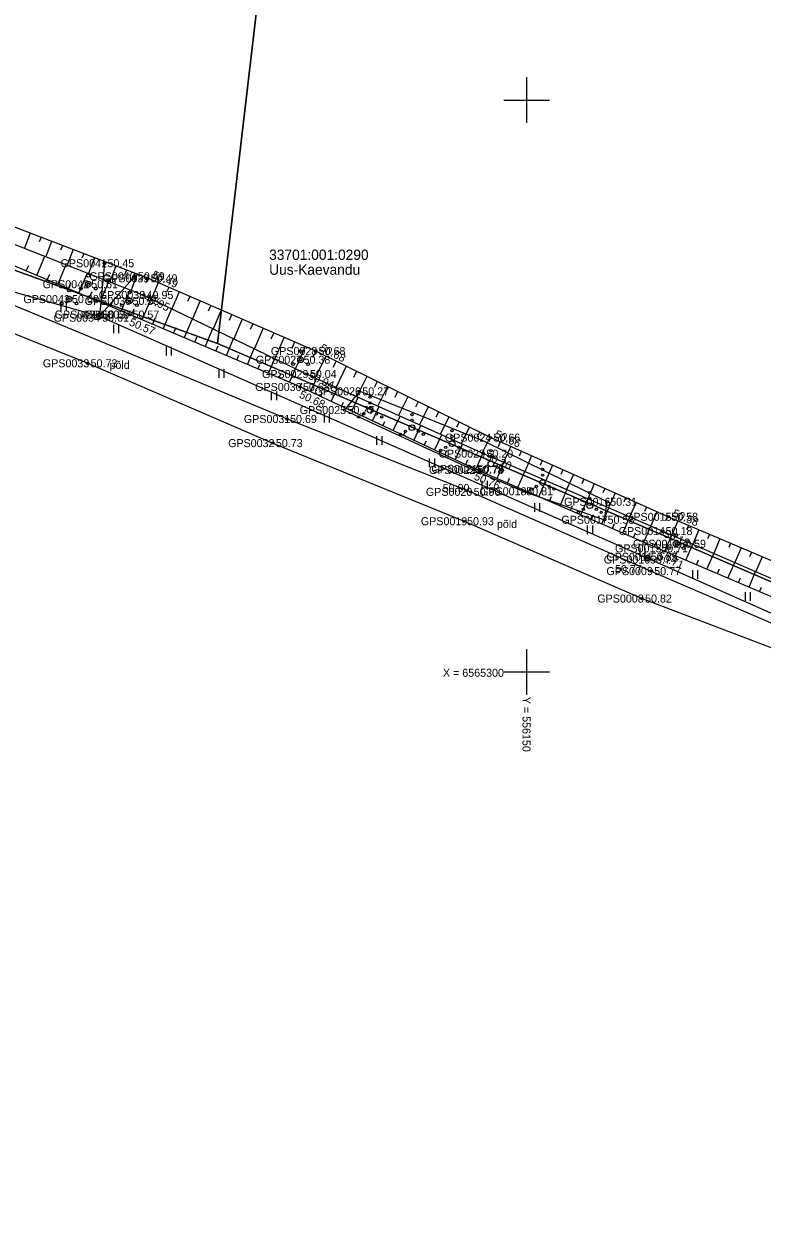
# Model space of a CAD drawing. Extents: x 551623 to 559850, y 6561220 to 6567135.
# Drawn here: x 556106 to 556170.6, y 6565252.6 to 6565356.7 of the extents above; entities that cross this region are included whole.
import ezdxf

# ---------------------------------------------------------------- set-up
doc = ezdxf.new("R2010")
doc.units = 0
for name, color, linetype in [('HALJASTUS', 7, 'Continuous'), ('KORGUS-EH2000', 7, 'Continuous'), ('KPOHULIIN', 7, 'Continuous'), ('MOOTKORG-EH2000', 7, 'Continuous'), ('MOOTMPUNKT', 7, 'Continuous'), ('MOOTNR', 7, 'Continuous'), ('MOOTPIIR', 7, 'Continuous'), ('PIIR', 7, 'Continuous'), ('POST', 7, 'Continuous'), ('PUU', 7, 'Continuous'), ('RELJEEF', 7, 'Continuous'), ('VORK', 7, 'Continuous')]:
    doc.layers.add(name, color=color, linetype=linetype)

msp = doc.modelspace()

# ---------------------------------------------------------------- linework, layer by layer
at = {"layer": 'HALJASTUS'}
for p, q in [((556109.26, 6565332.35), (556109.26, 6565331.59)), ((556109.72, 6565332.35), (556109.72, 6565331.59)), ((556113.87, 6565330.39), (556113.87, 6565329.63)), ((556114.32, 6565330.39), (556114.32, 6565329.63)), ((556118.47, 6565328.44), (556118.47, 6565327.68)), ((556118.92, 6565328.44), (556118.92, 6565327.68)), ((556123.07, 6565326.49), (556123.07, 6565325.73)), ((556123.53, 6565326.49), (556123.53, 6565325.73)), ((556127.67, 6565324.53), (556127.67, 6565323.77)), ((556128.13, 6565324.53), (556128.13, 6565323.77)), ((556132.28, 6565322.58), (556132.28, 6565321.82)), ((556132.73, 6565322.58), (556132.73, 6565321.82)), ((556136.88, 6565320.63), (556136.88, 6565319.87)), ((556137.33, 6565320.63), (556137.33, 6565319.87)), ((556141.48, 6565318.67), (556141.48, 6565317.91)), ((556141.94, 6565318.67), (556141.94, 6565317.91)), ((556146.09, 6565316.72), (556146.09, 6565315.96)), ((556146.54, 6565316.72), (556146.54, 6565315.96)), ((556150.69, 6565314.77), (556150.69, 6565314.01)), ((556151.14, 6565314.77), (556151.14, 6565314.01)), ((556155.29, 6565312.82), (556155.29, 6565312.05)), ((556155.75, 6565312.82), (556155.75, 6565312.05)), ((556159.89, 6565310.86), (556159.89, 6565310.1)), ((556160.35, 6565310.86), (556160.35, 6565310.1)), ((556164.5, 6565308.91), (556164.5, 6565308.15)), ((556164.95, 6565308.91), (556164.95, 6565308.15)), ((556169.1, 6565306.97), (556169.1, 6565306.21)), ((556169.56, 6565306.97), (556169.56, 6565306.21))]:
    msp.add_line(p, q, dxfattribs=at)
for points in [[(556046.78, 6565342.99), (556063.16, 6565343.59), (556068.98, 6565343.23), (556088, 6565339.17), (556129.05, 6565322.12), (556145.11, 6565315.75), (556160.9, 6565308.82), (556181.24, 6565300.03), (556189.31, 6565297.32), (556192.7, 6565293.43)], [(556157.05, 6565314.88), (556146.32, 6565320.15), (556135.37, 6565324.54), (556134.07, 6565322.9), (556145.38, 6565317.66), (556149.71, 6565315.8), (556156.82, 6565313.31), (556157.05, 6565314.88)]]:
    msp.add_lwpolyline(points, dxfattribs=at)
for centre, radius in [((556136.31, 6565324.03), 0.1), ((556136.31, 6565323.53), 0.1), ((556135.74, 6565322.55), 0.1), ((556136.31, 6565322.88), 0.25), ((556136.87, 6565322.55), 0.1), ((556139.97, 6565322.51), 0.1), ((556135.31, 6565322.3), 0.1), ((556137.31, 6565322.3), 0.1), ((556139.97, 6565321.36), 0.25), ((556139.97, 6565322.01), 0.1), ((556138.97, 6565320.78), 0.1), ((556139.4, 6565321.03), 0.1), ((556140.53, 6565321.03), 0.1), ((556140.97, 6565320.78), 0.1), ((556143.48, 6565321.11), 0.1), ((556143.48, 6565320.61), 0.1), ((556142.48, 6565319.39), 0.1), ((556142.92, 6565319.64), 0.1), ((556143.48, 6565319.96), 0.25), ((556144.05, 6565319.64), 0.1), ((556144.48, 6565319.39), 0.1), ((556146.88, 6565319.35), 0.1), ((556146.88, 6565318.2), 0.25), ((556146.88, 6565318.85), 0.1), ((556145.88, 6565317.63), 0.1), ((556146.31, 6565317.88), 0.1), ((556147.44, 6565317.88), 0.1), ((556147.88, 6565317.63), 0.1), ((556151.4, 6565317.71), 0.1), ((556150.84, 6565316.24), 0.1), ((556151.4, 6565316.56), 0.25), ((556151.4, 6565317.21), 0.1), ((556151.97, 6565316.24), 0.1), ((556150.4, 6565315.99), 0.1), ((556152.4, 6565315.99), 0.1), ((556155.52, 6565315.69), 0.1), ((556155.52, 6565315.19), 0.1), ((556154.96, 6565314.22), 0.1), ((556155.52, 6565314.54), 0.25), ((556156.09, 6565314.22), 0.1), ((556154.52, 6565313.97), 0.1), ((556156.52, 6565313.97), 0.1)]:
    msp.add_circle(centre, radius, dxfattribs=at)
at = {"layer": 'KORGUS-EH2000'}
for centre in [(556116.86, 6565334.42), (556116.5, 6565332.96), (556115.27, 6565331.25), (556131.55, 6565328.06), (556111.61, 6565326.99), (556130.78, 6565326.05), (556130.18, 6565324.92), (556129.05, 6565322.12), (556146.84, 6565320.49), (556127.81, 6565320.01), (556146.22, 6565319.09), (556145.45, 6565317.76), (556145.11, 6565315.75), (556144.53, 6565313.18), (556162.39, 6565313.57), (556161.9, 6565312.32), (556161.51, 6565310.81), (556160.9, 6565308.82), (556160.1, 6565306.42)]:
    msp.add_circle(centre, 0.1, dxfattribs=at)
at = {"layer": 'KPOHULIIN'}
msp.add_lwpolyline([(555766.29, 6565358.13), (555774.48, 6565357.81), (555774.48, 6565357.81), (555822.76, 6565358.14), (555870.36, 6565358.42), (555918.91, 6565358.62), (555918.91, 6565358.62), (555966.51, 6565359.06), (556012.01, 6565359.61), (556063.1, 6565345.17), (556063.1, 6565345.17), (556112.63, 6565331.11), (556160.57, 6565309.95), (556211.02, 6565287.53)], dxfattribs=at)
at = {"layer": 'MOOTMPUNKT'}
for centre in [(556113.08, 6565335.74), (556111.66, 6565333.9), (556115.74, 6565334.6), (556116.86, 6565334.42), (556116.5, 6565332.96), (556109.98, 6565332.6), (556115.27, 6565332.44), (556112.62, 6565330.98), (556112.64, 6565331.25), (556115.27, 6565331.25), (556131.55, 6565328.06), (556111.61, 6565326.99), (556130.23, 6565327.3), (556130.78, 6565326.05), (556130.18, 6565324.92), (556135.37, 6565324.54), (556134.07, 6565322.9), (556129.05, 6565322.12), (556146.84, 6565320.49), (556127.81, 6565320.01), (556146.22, 6565319.09), (556145.38, 6565317.66), (556145.45, 6565317.76), (556145.11, 6565315.75), (556149.71, 6565315.8), (556157.05, 6565314.88), (556144.53, 6565313.18), (556156.82, 6565313.31), (556162.39, 6565313.57), (556161.9, 6565312.32), (556163.08, 6565311.21), (556160.6, 6565310.07), (556161.51, 6565310.81), (556160.53, 6565309.83), (556160.9, 6565308.82), (556160.1, 6565306.42)]:
    msp.add_circle(centre, 0.1, dxfattribs=at)
at = {"layer": 'MOOTPIIR'}
for points in [[(556317.29, 6565325.67), (556298.01, 6565323.15), (556292.39, 6565325.24), (556233.7, 6565312.98), (556223.17, 6565308.85), (556214.05, 6565308.49), (556203.22, 6565309.4), (556197.61, 6565310.79), (556194.43, 6565307.33), (556191.93, 6565304.8), (556191.35, 6565302.57), (556183.62, 6565304.52), (556162.39, 6565313.57), (556146.84, 6565320.49), (556131.55, 6565328.06), (556116.86, 6565334.42), (556089.68, 6565344.85), (556063.9, 6565353.52), (556057.93, 6565353.82), (556039.2, 6565356.19)], [(556038.74, 6565344.78), (556063.16, 6565343.59), (556086.72, 6565336.99), (556111.61, 6565326.99), (556127.81, 6565320.01), (556144.53, 6565313.18), (556160.1, 6565306.42), (556180.24, 6565298.77), (556192.7, 6565293.43), (556201.96, 6565286.07), (556200.43, 6565280.1), (556196.23, 6565270.78), (556185.47, 6565248.99)]]:
    msp.add_lwpolyline(points, dxfattribs=at)
at = {"layer": 'PIIR'}
for points in [[(555860.69, 6565787.05), (556134.83, 6565867.67), (556136.76, 6565868.24), (556138.68, 6565868.81), (556304.72, 6565917.64), (556407.28, 6565947.65), (556409.2, 6565948.21), (556411.12, 6565948.77), (556555.39, 6565990.98), (556602.55, 6565855.41), (556340.11, 6565662.55), (556145.23, 6565518.55), (556122.95, 6565328.71), (556065.95, 6565349.3), (555986.85, 6565360.88), (555889.86, 6565359.34), (555877.35, 6565546.73)], [(556340.11, 6565662.55), (556389.4, 6565609.96), (556364.34, 6565374.53), (556350.73, 6565342.07), (556335.44, 6565331.24), (556229.81, 6565311.25), (556213.87, 6565303.19), (556199.38, 6565295.85), (556122.95, 6565328.71), (556145.23, 6565518.55)], [(555766.77, 6565362.31), (555785.15, 6565359.9), (555792.17, 6565359.86), (555889.86, 6565359.34), (555986.85, 6565360.88), (556065.95, 6565349.3), (556122.95, 6565328.71), (556199.38, 6565295.85), (556198.85, 6565282.81), (556195.83, 6565275.41), (556189.32, 6565262.35), (556176.88, 6565235.57), (556133.25, 6565139.15), (556097.67, 6565060.64), (555982.17, 6564796.57), (555965.54, 6564731.83), (555935.2, 6564801.96), (555871.92, 6565015.39), (555870.22, 6565021.13), (555867.36, 6565030.76)]]:
    msp.add_lwpolyline(points, close=True, dxfattribs=at)
at = {"layer": 'POST'}
msp.add_lwpolyline([(556113.08, 6565335.74), (556112.63, 6565331.11), (556115.74, 6565334.6)], dxfattribs=at)
for centre, radius in [((556113.08, 6565335.74), 0.125), ((556113.08, 6565335.74), 0.105), ((556113.08, 6565335.74), 0.0851), ((556113.08, 6565335.74), 0.0651), ((556113.08, 6565335.74), 0.0451), ((556113.08, 6565335.74), 0.0251), ((556113.08, 6565335.74), 0.00511), ((556115.74, 6565334.6), 0.125), ((556115.74, 6565334.6), 0.105), ((556115.74, 6565334.6), 0.0851), ((556115.74, 6565334.6), 0.0651), ((556115.74, 6565334.6), 0.0451), ((556115.74, 6565334.6), 0.0251), ((556115.74, 6565334.6), 0.00511), ((556112.63, 6565331.11), 0.25), ((556160.57, 6565309.95), 0.25)]:
    msp.add_circle(centre, radius, dxfattribs=at)
at = {"layer": 'PUU'}
for centre, radius in [((556111.66, 6565333.9), 0.25), ((556111.66, 6565334.65), 0.125), ((556109.98, 6565333.35), 0.125), ((556111.01, 6565333.52), 0.125), ((556112.31, 6565333.52), 0.125), ((556115.27, 6565333.19), 0.125), ((556109.33, 6565332.22), 0.125), ((556109.98, 6565332.6), 0.25), ((556110.63, 6565332.22), 0.125), ((556114.62, 6565332.07), 0.125), ((556115.27, 6565332.44), 0.25), ((556115.92, 6565332.07), 0.125), ((556130.23, 6565328.05), 0.125), ((556129.58, 6565326.92), 0.125), ((556130.23, 6565327.3), 0.25), ((556130.88, 6565326.92), 0.125), ((556163.08, 6565311.21), 0.25), ((556163.08, 6565311.96), 0.125), ((556162.43, 6565310.83), 0.125), ((556163.73, 6565310.83), 0.125)]:
    msp.add_circle(centre, radius, dxfattribs=at)
at = {"layer": 'RELJEEF'}
for p, q in [((556106.59, 6565338.36), (556106.09, 6565337.05)), ((556107.53, 6565338.01), (556107.38, 6565337.61)), ((556108.46, 6565337.65), (556107.95, 6565336.32)), ((556109.4, 6565337.29), (556109.24, 6565336.89)), ((556107.16, 6565334.67), (556107.87, 6565336.35)), ((556110.33, 6565336.93), (556109.81, 6565335.59)), ((556111.26, 6565336.57), (556111.11, 6565336.17)), ((556112.2, 6565336.21), (556111.67, 6565334.85)), ((556106.24, 6565335.06), (556106.45, 6565335.55)), ((556109, 6565333.89), (556109.73, 6565335.62)), ((556113.13, 6565335.86), (556112.97, 6565335.45)), ((556114.06, 6565335.5), (556113.54, 6565334.12)), ((556115, 6565335.14), (556114.84, 6565334.72)), ((556108.08, 6565334.28), (556108.3, 6565334.79)), ((556109.92, 6565333.5), (556110.14, 6565334.03)), ((556110.84, 6565333.11), (556111.59, 6565334.89)), ((556112.69, 6565332.34), (556113.45, 6565334.15)), ((556115.93, 6565334.78), (556115.4, 6565333.39)), ((556116.86, 6565334.42), (556116.69, 6565334.01)), ((556117.78, 6565334.02), (556117.18, 6565332.63)), ((556111.77, 6565332.73), (556111.99, 6565333.26)), ((556114.53, 6565331.56), (556115.32, 6565333.42)), ((556118.7, 6565333.63), (556118.51, 6565333.2)), ((556119.62, 6565333.23), (556118.98, 6565331.76)), ((556113.61, 6565331.95), (556113.84, 6565332.5)), ((556116.37, 6565330.78), (556117.16, 6565332.64)), ((556120.53, 6565332.83), (556120.34, 6565332.38)), ((556121.45, 6565332.44), (556120.78, 6565330.89)), ((556122.37, 6565332.04), (556122.16, 6565331.56)), ((556115.45, 6565331.17), (556115.69, 6565331.74)), ((556117.29, 6565330.39), (556117.52, 6565330.93)), ((556118.21, 6565330), (556118.96, 6565331.77)), ((556120.06, 6565329.22), (556120.77, 6565330.89)), ((556123.29, 6565331.64), (556122.58, 6565330.01)), ((556124.2, 6565331.24), (556123.99, 6565330.74)), ((556119.13, 6565329.61), (556119.35, 6565330.13)), ((556121.9, 6565328.44), (556122.57, 6565330.02)), ((556125.12, 6565330.85), (556124.38, 6565329.14)), ((556126.04, 6565330.45), (556125.81, 6565329.93)), ((556126.96, 6565330.05), (556126.19, 6565328.27)), ((556120.98, 6565328.83), (556121.18, 6565329.32)), ((556123.74, 6565327.66), (556124.37, 6565329.15)), ((556127.88, 6565329.65), (556127.64, 6565329.11)), ((556128.79, 6565329.26), (556127.99, 6565327.4)), ((556129.71, 6565328.86), (556129.46, 6565328.29)), ((556122.82, 6565328.05), (556123.01, 6565328.51)), ((556125.58, 6565326.88), (556126.17, 6565328.28)), ((556130.63, 6565328.46), (556129.79, 6565326.52)), ((556131.55, 6565328.06), (556131.26, 6565327.49)), ((556124.66, 6565327.27), (556124.84, 6565327.7)), ((556126.5, 6565326.48), (556126.67, 6565326.89)), ((556127.42, 6565326.09), (556127.98, 6565327.4)), ((556132.44, 6565327.62), (556131.5, 6565325.72)), ((556133.34, 6565327.18), (556133.06, 6565326.62)), ((556134.23, 6565326.73), (556133.33, 6565324.9)), ((556128.34, 6565325.7), (556128.5, 6565326.08)), ((556129.26, 6565325.31), (556129.78, 6565326.53)), ((556131.09, 6565324.5), (556131.63, 6565325.66)), ((556135.13, 6565326.29), (556134.86, 6565325.75)), ((556136.03, 6565325.84), (556135.15, 6565324.08)), ((556130.18, 6565324.92), (556130.34, 6565325.27)), ((556132.9, 6565323.65), (556133.46, 6565324.84)), ((556136.92, 6565325.4), (556136.66, 6565324.88)), ((556137.82, 6565324.96), (556136.98, 6565323.26)), ((556131.99, 6565324.07), (556132.16, 6565324.43)), ((556133.8, 6565323.22), (556133.97, 6565323.58)), ((556134.71, 6565322.8), (556135.28, 6565324.02)), ((556138.71, 6565324.51), (556138.47, 6565324.01)), ((556139.61, 6565324.07), (556138.8, 6565322.43)), ((556140.51, 6565323.62), (556140.27, 6565323.14)), ((556135.61, 6565322.37), (556135.79, 6565322.74)), ((556136.52, 6565321.95), (556137.1, 6565323.2)), ((556141.4, 6565323.18), (556140.63, 6565321.61)), ((556142.3, 6565322.73), (556142.07, 6565322.27)), ((556137.42, 6565321.52), (556137.6, 6565321.9)), ((556138.33, 6565321.1), (556138.93, 6565322.38)), ((556140.14, 6565320.25), (556140.75, 6565321.56)), ((556143.19, 6565322.29), (556142.45, 6565320.79)), ((556144.09, 6565321.85), (556143.87, 6565321.41)), ((556139.23, 6565320.67), (556139.42, 6565321.06)), ((556141.95, 6565319.4), (556142.58, 6565320.73)), ((556144.99, 6565321.4), (556144.28, 6565319.97)), ((556145.88, 6565320.96), (556145.67, 6565320.54)), ((556146.78, 6565320.51), (556146.1, 6565319.15)), ((556141.04, 6565319.83), (556141.23, 6565320.22)), ((556143.76, 6565318.55), (556144.4, 6565319.91)), ((556147.69, 6565320.11), (556147.51, 6565319.69)), ((556148.6, 6565319.7), (556147.99, 6565318.33)), ((556142.86, 6565318.98), (556143.05, 6565319.38)), ((556144.67, 6565318.13), (556144.86, 6565318.54)), ((556145.57, 6565317.71), (556146.18, 6565319.11)), ((556149.52, 6565319.29), (556149.34, 6565318.88)), ((556150.43, 6565318.89), (556149.83, 6565317.53)), ((556151.35, 6565318.48), (556151.17, 6565318.08)), ((556146.49, 6565317.31), (556146.67, 6565317.73)), ((556147.41, 6565316.91), (556148.02, 6565318.32)), ((556149.24, 6565316.12), (556149.85, 6565317.52)), ((556152.26, 6565318.07), (556151.67, 6565316.74)), ((556153.17, 6565317.67), (556153, 6565317.27)), ((556148.33, 6565316.51), (556148.51, 6565316.94)), ((556151.08, 6565315.32), (556151.69, 6565316.73)), ((556154.09, 6565317.26), (556153.5, 6565315.95)), ((556155, 6565316.85), (556154.83, 6565316.46)), ((556155.91, 6565316.45), (556155.34, 6565315.15)), ((556150.16, 6565315.72), (556150.34, 6565316.14)), ((556152, 6565314.93), (556152.18, 6565315.35)), ((556152.92, 6565314.53), (556153.52, 6565315.94)), ((556156.83, 6565316.04), (556156.66, 6565315.66)), ((556157.74, 6565315.64), (556157.17, 6565314.36)), ((556153.83, 6565314.13), (556154.02, 6565314.55)), ((556154.75, 6565313.74), (556155.36, 6565315.14)), ((556156.59, 6565312.94), (556157.2, 6565314.35)), ((556158.65, 6565315.23), (556158.49, 6565314.85)), ((556159.57, 6565314.82), (556159.01, 6565313.57)), ((556160.48, 6565314.42), (556160.32, 6565314.04)), ((556155.67, 6565313.34), (556155.85, 6565313.76)), ((556158.42, 6565312.15), (556159.03, 6565313.56)), ((556161.4, 6565314.01), (556160.85, 6565312.77)), ((556162.31, 6565313.6), (556162.15, 6565313.23)), ((556163.23, 6565313.21), (556162.7, 6565311.97)), ((556157.5, 6565312.54), (556157.69, 6565312.97)), ((556159.34, 6565311.75), (556159.52, 6565312.17)), ((556160.26, 6565311.35), (556160.87, 6565312.76)), ((556164.15, 6565312.82), (556163.99, 6565312.44)), ((556165.07, 6565312.43), (556164.53, 6565311.17)), ((556161.18, 6565310.96), (556161.36, 6565311.38)), ((556162.1, 6565310.56), (556162.7, 6565311.97)), ((556163.93, 6565309.78), (556164.53, 6565311.17)), ((556165.99, 6565312.03), (556165.83, 6565311.65)), ((556166.91, 6565311.64), (556166.37, 6565310.37)), ((556167.83, 6565311.25), (556167.67, 6565310.87)), ((556163.01, 6565310.17), (556163.19, 6565310.59)), ((556165.77, 6565308.99), (556166.36, 6565310.37)), ((556168.75, 6565310.86), (556168.2, 6565309.57)), ((556169.67, 6565310.46), (556169.5, 6565310.08)), ((556170.59, 6565310.07), (556170.04, 6565308.78)), ((556164.85, 6565309.38), (556165.03, 6565309.8)), ((556166.69, 6565308.6), (556166.87, 6565309.01)), ((556167.61, 6565308.21), (556168.2, 6565309.58)), ((556168.53, 6565307.81), (556168.71, 6565308.22)), ((556169.45, 6565307.42), (556170.03, 6565308.78)), ((556170.37, 6565307.03), (556170.55, 6565307.43))]:
    msp.add_line(p, q, dxfattribs=at)
for points in [[(556028.75, 6565357.94), (556030.86, 6565357.56), (556039.2, 6565356.19), (556057.93, 6565353.82), (556064.59, 6565351.83), (556088.94, 6565343.79), (556116.5, 6565332.96), (556130.78, 6565326.05), (556146.22, 6565319.09), (556161.9, 6565312.32), (556182.88, 6565303.19), (556190.09, 6565300.49), (556198.95, 6565296.14)], [(556198.95, 6565295.38), (556198.43, 6565295.22), (556190.12, 6565299.05), (556182.03, 6565302.05), (556161.51, 6565310.81), (556145.45, 6565317.76), (556130.18, 6565324.92), (556115.27, 6565331.25), (556088.43, 6565342.56), (556064.01, 6565350.43), (556058.39, 6565352.29), (556039.04, 6565355.08), (556031.39, 6565355.68), (556030.57, 6565354.76), (556029.12, 6565354.87), (556026.62, 6565346.44)], [(556199.48, 6565296.51), (556199.26, 6565296.85), (556195.09, 6565299.14), (556183.62, 6565304.52), (556162.39, 6565313.57), (556146.84, 6565320.49), (556131.55, 6565328.06), (556116.86, 6565334.42), (556089.68, 6565344.85), (556063.9, 6565353.52), (556057.92, 6565355.03)]]:
    msp.add_lwpolyline(points, dxfattribs=at)
at = {"layer": 'VORK'}
for p, q in [((556150, 6565352), (556150, 6565348)), ((556148, 6565350), (556152, 6565350)), ((556150, 6565302), (556150, 6565298)), ((556148, 6565300), (556152, 6565300))]:
    msp.add_line(p, q, dxfattribs=at)

# ---------------------------------------------------------------- texts
at = {"layer": 'HALJASTUS'}
for p in [(556113.52, 6565326.5), (556147.4, 6565312.59)]:
    msp.add_text('põld', height=0.7, dxfattribs=at).set_placement(p)
at = {"layer": 'KORGUS-EH2000'}
for s, rotation, p in [(' 50.49', 336.5818, (556116.93, 6565334.58)), (' 49.95', 334.1703, (556116.23, 6565332.64)), (' 50.57', 337.0012, (556114.93, 6565330.44)), (' 50.68', 333.6384, (556131.62, 6565328.22)), (' 50.04', 335.7578, (556130.6, 6565325.77)), (' 50.68', 334.8662, (556129.81, 6565324.13)), (' 50.66', 336.0193, (556146.91, 6565320.65)), (' 50.20', 336.6272, (556146.11, 6565318.68)), (' 50.76', 336.609, (556145.1, 6565316.96)), (' 50.58', 336.9079, (556162.46, 6565313.73)), (' 50.18', 336.4796, (556161.68, 6565311.94)), (' 50.71', 336.8869, (556161.16, 6565310.01))]:
    msp.add_text(s, height=0.7, rotation=rotation, dxfattribs=at).set_placement(p)
for s, p in [(' 50.73', (556111.61, 6565326.64)), (' 50.69', (556129.05, 6565321.77)), (' 50.73', (556127.81, 6565319.66)), (' 50.90', (556142.4, 6565315.74)), (' 50.93', (556144.53, 6565312.83)), (' 50.77', (556157.47, 6565308.64)), (' 50.82', (556160.1, 6565306.07))]:
    msp.add_text(s, height=0.7, dxfattribs=at).set_placement(p)
at = {"layer": 'MOOTKORG-EH2000'}
for s, p in [(' 50.45', (556113.08, 6565335.39)), (' 50.61', (556111.66, 6565333.55)), (' 50.49', (556115.74, 6565334.25)), (' 50.49', (556116.86, 6565334.07)), (' 50.68', (556109.98, 6565332.25)), (' 49.95', (556116.5, 6565332.61)), (' 50.53', (556115.27, 6565332.09)), (' 50.61', (556112.62, 6565330.63)), (' 50.69', (556112.64, 6565330.9)), (' 50.57', (556115.27, 6565330.9)), (' 50.68', (556131.55, 6565327.71)), (' 50.73', (556111.61, 6565326.64)), (' 50.38', (556130.23, 6565326.95)), (' 50.04', (556130.78, 6565325.7)), (' 50.68', (556130.18, 6565324.57)), (' 50.27', (556135.37, 6565324.19)), (' 50.77', (556134.07, 6565322.55)), (' 50.69', (556129.05, 6565321.77)), (' 50.66', (556146.84, 6565320.14)), (' 50.73', (556127.81, 6565319.66)), (' 50.20', (556146.22, 6565318.74)), (' 50.78', (556145.38, 6565317.31)), (' 50.76', (556145.45, 6565317.41)), (' 50.90', (556145.11, 6565315.4)), (' 50.81', (556149.71, 6565315.45)), (' 50.31', (556157.05, 6565314.53)), (' 50.93', (556144.53, 6565312.83)), (' 50.58', (556156.82, 6565312.96)), (' 50.58', (556162.39, 6565313.22)), (' 50.18', (556161.9, 6565311.97)), (' 50.71', (556161.51, 6565310.46)), (' 50.59', (556163.08, 6565310.86)), (' 50.74', (556160.53, 6565309.48)), (' 50.85', (556160.6, 6565309.72)), (' 50.77', (556160.9, 6565308.47)), (' 50.82', (556160.1, 6565306.07))]:
    msp.add_text(s, height=0.7, dxfattribs=at).set_placement(p)
at = {"layer": 'MOOTNR'}
for s, p in [('GPS0041 ', (556109.24, 6565335.39)), ('GPS0042 ', (556107.67, 6565333.55)), ('GPS0040 ', (556111.75, 6565334.25)), ('GPS0039 ', (556112.94, 6565334.07)), ('GPS0043 ', (556105.99, 6565332.25)), ('GPS0038 ', (556112.58, 6565332.61)), ('GPS0036 ', (556111.35, 6565332.09)), ('GPS0034 ', (556108.63, 6565330.63)), ('GPS0035 ', (556108.72, 6565330.9)), ('GPS0037 ', (556111.35, 6565330.9)), ('GPS0028 ', (556127.63, 6565327.71)), ('GPS0033 ', (556107.69, 6565326.64)), ('GPS0027 ', (556126.31, 6565326.95)), ('GPS0029 ', (556126.86, 6565325.7)), ('GPS0030 ', (556126.26, 6565324.57)), ('GPS0026 ', (556131.45, 6565324.19)), ('GPS0025 ', (556130.15, 6565322.55)), ('GPS0031 ', (556125.27, 6565321.77)), ('GPS0024 ', (556142.85, 6565320.14)), ('GPS0032 ', (556123.89, 6565319.66)), ('GPS0023 ', (556142.3, 6565318.74)), ('GPS0022 ', (556141.46, 6565317.31)), ('GPS0021 ', (556141.67, 6565317.41)), ('GPS0020 ', (556141.19, 6565315.4)), ('GPS0018 ', (556145.93, 6565315.45)), ('GPS0016 ', (556153.27, 6565314.53)), ('GPS0019 ', (556140.75, 6565312.83)), ('GPS0017 ', (556153.04, 6565312.96)), ('GPS0015 ', (556158.61, 6565313.22)), ('GPS0014 ', (556158.05, 6565311.97)), ('GPS0013 ', (556157.73, 6565310.46)), ('GPS0012 ', (556159.3, 6565310.86)), ('GPS0010 ', (556156.75, 6565309.48)), ('GPS0011 ', (556156.97, 6565309.72)), ('GPS0009 ', (556156.98, 6565308.47)), ('GPS0008 ', (556156.18, 6565306.07))]:
    msp.add_text(s, height=0.7, dxfattribs=at).set_placement(p)
at = {"layer": 'PIIR'}
for s, p in [('33701:001:0290', (556127.48, 6565336.03)), ('Uus-Kaevandu', (556127.48, 6565334.73))]:
    msp.add_text(s, height=0.9, dxfattribs=at).set_placement(p)
at = {"layer": 'VORK'}
msp.add_text('X = 6565300', height=0.7, dxfattribs=at).set_placement((556142.68, 6565299.58))
msp.add_text('Y = 556150 ', height=0.7, rotation=270, dxfattribs=at).set_placement((556149.64, 6565297.83))

doc.saveas('drawing.dxf')
